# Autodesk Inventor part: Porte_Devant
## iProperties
Created: 2009-01
Part Number: Porte_Devant
Document SubType Name: Sheet Metal
Designer: claivier
Author: claivier
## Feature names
1. Extrusion1
2. Miroir1 [Mirror]
3. Extrusion3
4. Miroir2 [Mirror]
5. Perçage1 [Hole]
6. Perçage2 [Hole]
7. Perçage3 [Hole]
8. Extrusion6
9. Plaque1
10. Pli1
11. Plaque3
12. Pli3
13. Couper1
14. Couper3
15. Couper5
16. Couper6
17. Couper8
18. Couper9
19. Couper10
20. Couper11
21. Couper12
22. Couper13
